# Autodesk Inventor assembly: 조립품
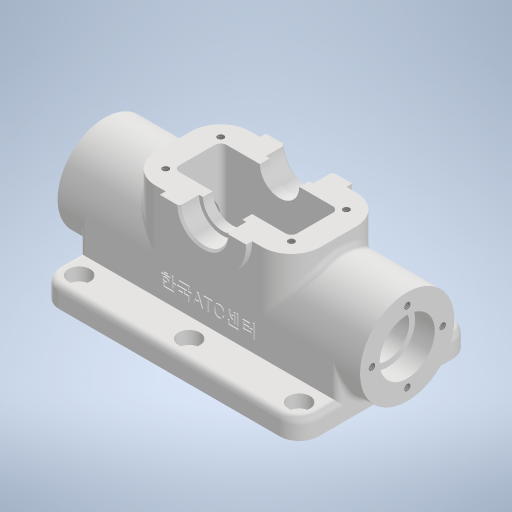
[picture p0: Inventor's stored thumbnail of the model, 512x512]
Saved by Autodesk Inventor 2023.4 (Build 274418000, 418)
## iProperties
Created: 2024-06
Part Number: 조립품
Document SubType Name: Assembly
Designer: edu-40
Author: edu-40
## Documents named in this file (2)
- C:\Users\edu-40\Desktop\740604V1003\조립품.iam
- C:\Users\edu-40\Desktop\740604V1003\본체.ipt
